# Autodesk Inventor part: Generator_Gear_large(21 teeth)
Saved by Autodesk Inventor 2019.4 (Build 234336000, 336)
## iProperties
Created: 2020-02
Part Number: Generator_Gear_large(21 teeth)
Material: Generic
Description: Spur Gear; Module: 0.900000; Num Teeth: 21; Pressure Angle: 20.000000; Backlash: 0.00 mm
Document SubType Name: Modeling
Designer: Administrator
Density: 1 g/cm^3
Appearance: Default
Title: Generator_Gear_large(21 teeth) v4
Author: Administrator
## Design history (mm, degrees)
feature "Body1"
body "Solid1"
